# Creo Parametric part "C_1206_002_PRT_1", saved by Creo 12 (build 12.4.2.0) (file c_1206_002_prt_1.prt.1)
Units: Custom; MM, KILOGRAM, SECS

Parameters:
  PTC_WM_ITERATION = "0"
  PTC_WM_VERSION = "-.0"
  PTC_WM_LIFECYCLE_STATE = "In Work"
  PTC_WM_LIFECYCLE = "MO_CADDocument"
  PTC_WM_CREATED_BY = "Maximilian Roepper (Z0017RMS: MO)"
  PTC_WM_CREATED_ON = "18-Sep-26 11:36:42 AM"
  PTC_WM_MODIFIED_BY = "Maximilian Roepper (Z0017RMS: MO)"
  PTC_WM_MODIFIED_ON = "18-Sep-26 11:36:46 AM"
  PDMLINKNUMBER = "PDM000071454915"
  PTC_WM_NAME = "c_1206_002_prt_1.prt"
  PTC_WM_NUMBER = "PDM000071454915"

Other parameters: WEIGHT, WEIGHT_FACTOR, WEIGHT_ADD, _MASS_TEMP, _DIFF_TEMP, MC_ERRORS, SUPPLIER

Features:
  1. coordinate system
  2. datum plane "PRT_YZ"
  3. datum plane "PRT_XY"
  4. datum plane "PRT_XZ"
  5. coordinate system
  6. datum axis
  7. datum axis
  8. datum axis
  9. coordinate system
  10. imported feature
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
Other named items: PRT, SIEMENS_MO, DRW_VIEW_ORG, PRT_X, PRT_Y, PRT_Z, CS0, ROUGH_GROB

Layers: 00_STD_CSYS-KSYS, 01_STD_PLANES-EBENEN, 02_STD_AXES-ACHSEN, 03_STD_CSYS-KSYS, 24_IMPORT_FEAT-IMPORT_KE

Surfaces: 16 plane, 12 cylinder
